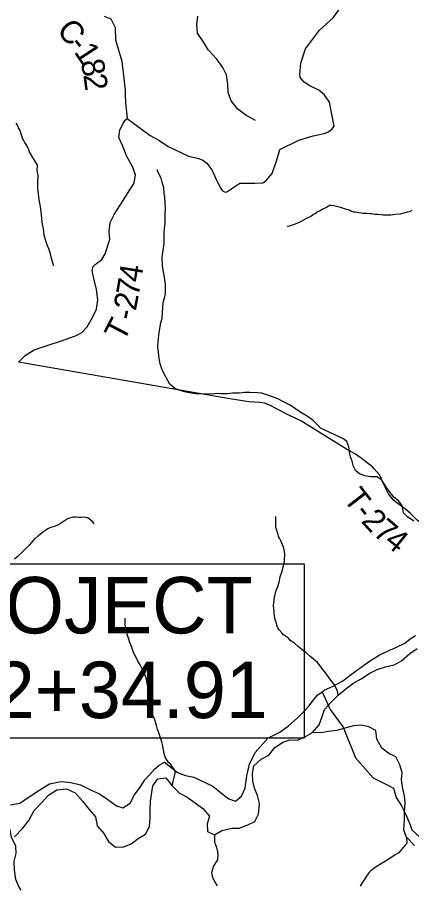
# Model space of a CAD drawing. Extents: x 0 to 34, y 0 to 22.
# Drawn here: x 6.694 to 7.671, y 15.248 to 17.398 of the extents above; entities that cross this region are included whole.
import ezdxf

# ---------------------------------------------------------------- set-up
doc = ezdxf.new("R2010")
doc.units = 0
for name, color, linetype in [('GM_X_County_Road', 7, 'Continuous'), ('GM_X_County_Road_Text', 7, 'Continuous'), ('GM_X_Major_River', 7, 'Continuous'), ('GM_X_Minor_River', 7, 'Continuous'), ('GM_X_Township_Road', 7, 'Continuous'), ('GM_X_Township_Road_Text', 7, 'Continuous'), ('SH_Masking', 7, 'Continuous'), ('SH_Text', 7, 'Continuous')]:
    doc.layers.add(name, color=color, linetype=linetype)

msp = doc.modelspace()

# ---------------------------------------------------------------- linework, layer by layer
at = {"layer": 'GM_X_County_Road'}
for points in [[(6.9615, 17.2059), (6.9619, 17.1873), (6.9657, 17.148), (7.0231, 17.1057), (7.0448, 17.0937), (7.0678, 17.078), (7.0956, 17.0653), (7.1185, 17.0545), (7.144, 17.0486), (7.1534, 17.0446), (7.1635, 17.0366), (7.1762, 17.0208), (7.1901, 16.9901), (7.1979, 16.9738), (7.2028, 16.9683), (7.209, 16.9652), (7.2135, 16.9656), (7.2453, 16.9872), (7.2829, 16.9875), (7.3023, 16.9884), (7.3096, 16.993), (7.3209, 17.0055), (7.3253, 17.0115), (7.3375, 17.0454), (7.3449, 17.0709), (7.3918, 17.0941), (7.4274, 17.1047), (7.4548, 17.1103), (7.4653, 17.1149), (7.4746, 17.1224), (7.4789, 17.1284), (7.4678, 17.1883), (7.4546, 17.2069), (7.4413, 17.2181), (7.4188, 17.229), (7.4046, 17.2376), (7.3953, 17.2494), (7.3942, 17.2565), (7.3966, 17.285), (7.4081, 17.3201), (7.443, 17.3664), (7.477, 17.3975), (7.4972, 17.4258)], [(6.909, 17.4016), (6.9255, 17.3945), (6.9367, 17.3737), (6.937, 17.3429), (6.9527, 17.2902), (6.9613, 17.2177), (6.9615, 17.2059)], [(6.6999, 15.4504), (6.7429, 15.4793), (6.7737, 15.4979), (6.8022, 15.5039), (6.8261, 15.502), (6.8504, 15.4955), (6.8754, 15.4834), (6.8975, 15.4731), (6.9183, 15.4598), (6.94, 15.4435), (6.9552, 15.4385), (6.9738, 15.4507), (6.9844, 15.4712), (6.9981, 15.4898), (7.0095, 15.508), (7.0225, 15.5217), (7.035, 15.5353), (7.0456, 15.5448), (7.0582, 15.5524), (7.0745, 15.5395), (7.0912, 15.5262), (7.1106, 15.5186), (7.1311, 15.5148), (7.1785, 15.4924), (7.2009, 15.4745), (7.2184, 15.4608), (7.2347, 15.4555), (7.2495, 15.4677), (7.2583, 15.4878), (7.2625, 15.5181), (7.269, 15.547), (7.2834, 15.5759), (7.315, 15.6112), (7.3442, 15.6267), (7.3659, 15.6423), (7.3876, 15.6613), (7.4058, 15.6791), (7.4172, 15.6916), (7.4256, 15.703), (7.4389, 15.7186), (7.4491, 15.7265), (7.4545, 15.7307), (7.4788, 15.741), (7.5008, 15.7539), (7.5221, 15.7702), (7.5666, 15.8028), (7.5905, 15.8172), (7.6099, 15.8267), (7.6338, 15.8374), (7.6547, 15.8472), (7.668, 15.8575), (7.6806, 15.8662)], [(6.6768, 15.4459), (6.6999, 15.4504)]]:
    msp.add_lwpolyline(points, dxfattribs=at)
at = {"layer": 'GM_X_Major_River'}
for points in [[(7.0234, 15.4144), (7.0227, 15.4349), (7.0235, 15.4546), (7.0266, 15.472), (7.0297, 15.4932), (7.0419, 15.5106), (7.0623, 15.5128), (7.0774, 15.4931), (7.0955, 15.4748), (7.1144, 15.4649), (7.1348, 15.4512), (7.1537, 15.4375), (7.1703, 15.4185), (7.1642, 15.3988), (7.1649, 15.3798), (7.1822, 15.3722), (7.2004, 15.3828), (7.2262, 15.3888), (7.2436, 15.3887), (7.2648, 15.397), (7.2823, 15.4053), (7.2914, 15.4227), (7.2938, 15.4492), (7.2893, 15.4697), (7.2818, 15.4872), (7.2773, 15.5046), (7.2766, 15.5236), (7.2797, 15.5426), (7.2986, 15.5592), (7.3176, 15.5697), (7.3313, 15.5879), (7.3518, 15.6015), (7.3692, 15.6075), (7.3881, 15.6067), (7.4078, 15.6157), (7.4253, 15.6256), (7.442, 15.6445), (7.4496, 15.6649), (7.455, 15.6823), (7.4709, 15.6997), (7.4891, 15.7179), (7.5081, 15.7338), (7.5256, 15.7474), (7.546, 15.7587), (7.5673, 15.7723), (7.5855, 15.7821), (7.6067, 15.7881), (7.6279, 15.7933), (7.6461, 15.8031), (7.6666, 15.8213), (7.6848, 15.8341)], [(6.6864, 15.3668), (6.7062, 15.3873), (6.7221, 15.4077), (6.7358, 15.4319), (6.754, 15.4508), (6.7708, 15.4705), (6.792, 15.4833), (6.8155, 15.4863), (6.8374, 15.4763), (6.8562, 15.4543), (6.8721, 15.4345), (6.8872, 15.4163), (6.8916, 15.3943), (6.9082, 15.3753), (6.9195, 15.3555), (6.9369, 15.3411), (6.9581, 15.3425), (6.9763, 15.3493), (6.9937, 15.3629), (7.0112, 15.3735), (7.0211, 15.3924), (7.0234, 15.4144)]]:
    msp.add_lwpolyline(points, dxfattribs=at)
at = {"layer": 'GM_X_Minor_River'}
for points in [[(7.2846, 17.1431), (7.2605, 17.1561), (7.2408, 17.1706), (7.2235, 17.1919), (7.2167, 17.2124), (7.216, 17.2329), (7.2123, 17.2557), (7.2033, 17.2739), (7.1882, 17.2944), (7.1671, 17.318), (7.1558, 17.3363), (7.1407, 17.3591), (7.1385, 17.3804), (7.1409, 17.4016)], [(6.6899, 17.1364), (6.694, 17.1306), (6.6969, 17.123), (6.6998, 17.1184), (6.7023, 17.11), (6.7063, 17.0974), (6.7092, 17.0931), (6.7118, 17.0882), (6.7151, 17.0832), (6.7188, 17.0766), (6.7214, 17.0705), (6.7239, 17.0636)], [(6.7239, 17.0636), (6.7429, 17.0316), (6.7425, 17.0187), (6.7444, 17.0066), (6.744, 16.9888), (6.7436, 16.9744), (6.7452, 16.9607), (6.7474, 16.946), (6.7493, 16.9335), (6.7512, 16.9232), (6.7527, 16.9107), (6.7538, 16.8978), (6.7554, 16.8861), (6.7576, 16.8739), (6.7595, 16.8595), (6.7629, 16.8474), (6.7667, 16.8357), (6.7709, 16.8258), (6.7746, 16.8152), (6.7765, 16.805), (6.7799, 16.7928), (6.7837, 16.7834), (6.7837, 16.7837)], [(7.6771, 16.1491), (7.6608, 16.1604), (7.6514, 16.1699), (7.6495, 16.1797), (7.6468, 16.1892), (7.6385, 16.1998), (7.6268, 16.2089), (7.6188, 16.2195), (7.6105, 16.2301), (7.5977, 16.251), (7.5848, 16.2593), (7.5693, 16.2597), (7.5556, 16.262), (7.5424, 16.2665), (7.5322, 16.2748), (7.5269, 16.2851), (7.5235, 16.2983), (7.5193, 16.3112), (7.5171, 16.3218), (7.5155, 16.334), (7.5103, 16.3468), (7.5004, 16.3548), (7.4838, 16.362), (7.4671, 16.3699), (7.4561, 16.3753), (7.4455, 16.3798), (7.4372, 16.3893), (7.4262, 16.3995), (7.4119, 16.4097), (7.3967, 16.4188), (7.3831, 16.4279), (7.3699, 16.437), (7.3555, 16.4442), (7.3392, 16.4525), (7.3195, 16.4605), (7.3097, 16.4635), (7.2995, 16.4666), (7.2889, 16.4677), (7.2703, 16.4685), (7.2575, 16.4681), (7.2435, 16.4669), (7.2276, 16.4666), (7.2136, 16.4654), (7.1988, 16.4651), (7.1886, 16.4658), (7.1746, 16.4647), (7.1572, 16.4651), (7.1401, 16.4647), (7.1258, 16.4666), (7.1121, 16.4696), (7.0974, 16.473), (7.0841, 16.4787), (7.0716, 16.4893), (7.0584, 16.5128), (7.0516, 16.5272), (7.0478, 16.5393), (7.0455, 16.5533), (7.0437, 16.5674), (7.0422, 16.5825), (7.0437, 16.6034), (7.0456, 16.6162), (7.0467, 16.6272), (7.0497, 16.6413), (7.0528, 16.653), (7.0535, 16.667), (7.0543, 16.6788), (7.055, 16.6917), (7.0588, 16.7023), (7.0607, 16.714), (7.0615, 16.7239), (7.0615, 16.7368), (7.0596, 16.7474), (7.0581, 16.7591), (7.0551, 16.7716), (7.0539, 16.7834), (7.0532, 16.8046), (7.0551, 16.8205), (7.0577, 16.8376), (7.0581, 16.8504), (7.0577, 16.8645), (7.0589, 16.8758), (7.06, 16.8876), (7.0604, 16.8978), (7.0604, 16.9103), (7.0612, 16.9247), (7.0604, 16.938), (7.0593, 16.952), (7.0581, 16.963), (7.057, 16.9755), (7.0532, 16.9896), (7.0502, 16.9994), (7.0449, 17.0108), (7.0408, 17.0203), (7.0404, 17.0191)], [(7.6717, 16.9196), (7.6659, 16.9163), (7.6599, 16.9152), (7.6522, 16.9127), (7.6431, 16.9109), (7.6306, 16.9093), (7.6253, 16.9086), (7.6196, 16.9083), (7.6094, 16.9081), (7.5999, 16.9083), (7.595, 16.9087), (7.5878, 16.9096), (7.5802, 16.9101), (7.5723, 16.9114), (7.5674, 16.9115), (7.5591, 16.9124), (7.5515, 16.9125), (7.547, 16.9129), (7.5402, 16.9142), (7.5322, 16.9151), (7.5281, 16.9159), (7.5224, 16.9175), (7.5183, 16.9195), (7.5107, 16.9219), (7.5051, 16.9235), (7.4979, 16.9259), (7.4919, 16.9276), (7.4855, 16.9299), (7.4787, 16.9316), (7.4719, 16.9321), (7.4677, 16.9318), (7.4624, 16.9284), (7.4582, 16.9262), (7.4509, 16.9233), (7.4429, 16.9177), (7.4375, 16.9155), (7.4322, 16.9115), (7.428, 16.9096), (7.4211, 16.9044), (7.4138, 16.9011), (7.4073, 16.8978), (7.4012, 16.8945), (7.3954, 16.8912), (7.3882, 16.8879), (7.3825, 16.8857), (7.3779, 16.8843), (7.3726, 16.8821), (7.368, 16.881), (7.363, 16.8799)], [(6.6865, 16.0564), (6.6957, 16.0639), (6.7038, 16.0713), (6.7088, 16.0758), (6.7165, 16.0836), (6.7238, 16.09), (6.7296, 16.0967), (6.7342, 16.1016), (6.7381, 16.1061), (6.7454, 16.1135), (6.7523, 16.1187), (6.7593, 16.1243), (6.7666, 16.1299), (6.7708, 16.1317), (6.7803, 16.1354), (6.7868, 16.1368), (6.7955, 16.1416), (6.8005, 16.1449), (6.8055, 16.1478), (6.8097, 16.1504), (6.8174, 16.1556), (6.8239, 16.1578), (6.8326, 16.1599), (6.8398, 16.1602), (6.8455, 16.1597), (6.8527, 16.1596), (6.8569, 16.1603), (6.8629, 16.1594), (6.8674, 16.1582), (6.8719, 16.1558), (6.8786, 16.15), (6.8838, 16.1431)], [(7.4891, 15.7179), (7.4875, 15.7288), (7.4846, 15.7349), (7.4813, 15.7429), (7.4735, 15.7522), (7.4668, 15.761), (7.4617, 15.7676), (7.4561, 15.776), (7.4506, 15.7826), (7.4446, 15.7906), (7.4376, 15.7991), (7.4279, 15.8076), (7.4193, 15.815), (7.41, 15.8228), (7.3999, 15.8309), (7.3898, 15.839), (7.3809, 15.8472), (7.37, 15.8538), (7.3659, 15.8592), (7.3539, 15.8674), (7.3495, 15.8728), (7.3428, 15.8801), (7.3388, 15.887), (7.337, 15.892), (7.3359, 15.8969), (7.333, 15.9057), (7.3317, 15.9145), (7.3306, 15.9202), (7.3303, 15.9244), (7.3293, 15.9327), (7.3291, 15.9403), (7.3296, 15.9472), (7.3305, 15.9544), (7.3317, 15.9616), (7.333, 15.9672), (7.3342, 15.9725), (7.3366, 15.9793), (7.3394, 15.9876), (7.3426, 15.9986), (7.3455, 16.0115), (7.3503, 16.0251), (7.3528, 16.0364), (7.3552, 16.0455), (7.356, 16.0508), (7.3565, 16.0569), (7.357, 16.0629), (7.3571, 16.069), (7.3554, 16.0785), (7.354, 16.0846), (7.3514, 16.0911), (7.3478, 16.0992), (7.3434, 16.1076), (7.3416, 16.1118), (7.3401, 16.116), (7.3387, 16.1217), (7.3362, 16.1294), (7.3348, 16.1339), (7.3349, 16.1613)], [(7.0774, 15.4931), (7.0851, 15.5248), (7.0847, 15.529), (7.0826, 15.5347), (7.0781, 15.5398), (7.0741, 15.5459), (7.0688, 15.5509), (7.0663, 15.5551), (7.0615, 15.5628), (7.0593, 15.5674), (7.0579, 15.5739), (7.0565, 15.5823), (7.0548, 15.5907), (7.0534, 15.596), (7.0516, 15.6025), (7.0498, 15.6097), (7.0469, 15.6174), (7.0455, 15.6223), (7.044, 15.6269), (7.0415, 15.6334), (7.0387, 15.6433), (7.0369, 15.6491), (7.0343, 15.6567), (7.0314, 15.664), (7.0289, 15.6708), (7.0268, 15.6781), (7.025, 15.6846), (7.0241, 15.6964), (7.023, 15.7017), (7.0217, 15.712), (7.02, 15.7219), (7.019, 15.731), (7.0173, 15.7405), (7.0159, 15.7474), (7.0148, 15.7524), (7.0138, 15.7577), (7.0113, 15.7653), (7.008, 15.7734), (7.0036, 15.7833), (6.9981, 15.7933), (6.9922, 15.8025), (6.9864, 15.8144), (6.982, 15.8236), (6.9784, 15.8335), (6.9755, 15.843), (6.9722, 15.8503), (6.9705, 15.8579), (6.9668, 15.866), (6.9651, 15.874), (6.9629, 15.882), (6.9623, 15.8862), (6.9613, 15.8938), (6.9611, 15.9094)], [(7.6787, 15.3457), (7.6583, 15.3663), (7.6523, 15.3837), (7.6532, 15.4088), (7.654, 15.43), (7.6556, 15.4512), (7.6534, 15.4687), (7.6496, 15.4861), (7.6459, 15.5081), (7.6475, 15.5263), (7.6423, 15.5453), (7.6325, 15.565), (7.6151, 15.5734), (7.597, 15.5871), (7.5849, 15.6092), (7.5827, 15.6304), (7.5653, 15.6396), (7.5472, 15.6434), (7.5275, 15.6419), (7.5055, 15.6367), (7.4858, 15.6307), (7.4654, 15.6277), (7.4465, 15.6247), (7.4253, 15.6256)], [(7.1822, 15.3722), (7.1828, 15.3527), (7.1853, 15.3481), (7.1875, 15.3404), (7.1903, 15.3294), (7.1909, 15.321), (7.1904, 15.3149), (7.1896, 15.3096), (7.1869, 15.3051), (7.1826, 15.2987), (7.1794, 15.2931), (7.1778, 15.2863), (7.1754, 15.2787), (7.1771, 15.2692), (7.1807, 15.2593), (7.1852, 15.252), (7.1888, 15.2455)], [(7.6583, 15.3663), (7.6592, 15.3503), (7.6546, 15.3454), (7.6507, 15.3406), (7.6465, 15.3357), (7.6395, 15.3274), (7.6307, 15.3219), (7.6223, 15.3167), (7.6127, 15.3108), (7.602, 15.3038), (7.5943, 15.2994), (7.5836, 15.2927), (7.5771, 15.2879), (7.5705, 15.2823), (7.5651, 15.2774), (7.5613, 15.2722), (7.555, 15.2628), (7.5492, 15.2542), (7.5441, 15.2448)]]:
    msp.add_lwpolyline(points, dxfattribs=at)
at = {"layer": 'GM_X_Township_Road'}
msp.add_line((7.2207, 16.4531), (6.7536, 16.5335), dxfattribs=at)
for points in [[(6.881, 16.7625), (6.8792, 16.7708), (6.8815, 16.781), (6.8898, 16.7886), (6.9032, 16.7981), (6.9119, 16.8125), (6.9229, 16.8475), (6.9218, 16.8676), (6.9241, 16.89), (6.934, 16.9098), (6.9564, 16.9447), (6.9709, 16.9687), (6.9834, 16.9877), (6.9865, 17.0078), (6.9793, 17.0291), (6.9649, 17.0534), (6.9543, 17.0804), (6.9452, 17.1005), (6.9479, 17.1188), (6.9551, 17.1347), (6.9612, 17.1435), (6.9657, 17.148)], [(6.7536, 16.5335), (6.6967, 16.5433), (6.7134, 16.5604), (6.7358, 16.5741), (6.7723, 16.587), (6.8008, 16.5961), (6.8213, 16.6029), (6.838, 16.609), (6.8525, 16.6162), (6.8666, 16.6314), (6.8799, 16.6542), (6.8898, 16.6754), (6.8936, 16.6978), (6.8902, 16.7237), (6.8841, 16.748), (6.881, 16.7625)], [(7.5441, 16.3069), (7.5321, 16.3159), (7.5097, 16.3277), (7.4448, 16.3683), (7.3966, 16.3984), (7.3654, 16.4132), (7.3377, 16.4272), (7.321, 16.436), (7.3062, 16.4417), (7.2959, 16.444), (7.2675, 16.4451), (7.2207, 16.4531)], [(7.7559, 16.1046), (7.7328, 16.1199), (7.7028, 16.1385), (7.6858, 16.1514), (7.6687, 16.1685), (7.6558, 16.1795), (7.6379, 16.1924), (7.6266, 16.2015), (7.6137, 16.2171), (7.603, 16.2388), (7.5913, 16.2642), (7.5784, 16.2795), (7.5746, 16.284), (7.5611, 16.2941), (7.5484, 16.3037), (7.5441, 16.3069)], [(7.4491, 15.7265), (7.4691, 15.6826), (7.5015, 15.6388), (7.532, 15.5626), (7.5758, 15.5131), (7.612, 15.4947)], [(7.612, 15.4947), (7.6267, 15.4872), (7.6328, 15.4648), (7.646, 15.444), (7.6559, 15.4242), (7.6676, 15.3965), (7.6718, 15.3843), (7.6915, 15.3661), (7.7405, 15.3239), (7.7614, 15.3095), (7.7826, 15.2996), (7.8024, 15.2882), (7.8157, 15.2758)], [(6.703, 15.2346), (6.6971, 15.2435), (6.6903, 15.2613), (6.6869, 15.2849), (6.6861, 15.3058), (6.6907, 15.3255), (6.69, 15.3441), (6.6797, 15.3658), (6.6718, 15.4022), (6.6604, 15.447)]]:
    msp.add_lwpolyline(points, dxfattribs=at)
at = {"layer": 'SH_Masking'}
msp.add_lwpolyline([(5.9375, 16.0436), (7.4049, 16.0436), (7.4049, 15.6115), (5.9375, 15.6115)], close=True, dxfattribs=at)
at = {"layer": 'SH_Text'}
msp.add_lwpolyline([(5.9375, 16.0436), (7.4049, 16.0436), (7.4049, 15.6115), (5.9375, 15.6115)], close=True, dxfattribs=at)

# ---------------------------------------------------------------- texts
at = {"layer": 'GM_X_County_Road_Text'}
for s, rotation, p in [('C', 310.096, (6.7892, 17.3653)), ('-', 309.2096, (6.8191, 17.3298)), ('1', 303.5999, (6.833, 17.3129)), ('8', 282.191, (6.8502, 17.2889)), ('2', 277.1533, (6.8574, 17.256))]:
    msp.add_text(s, height=0.0568, rotation=rotation, dxfattribs=at).set_placement(p)
at = {"layer": 'GM_X_Township_Road_Text'}
for s, rotation, p in [('4', 80.5428, (7, 16.7394)), ('7', 80.3334, (6.9941, 16.7047)), ('2', 79.4819, (6.9875, 16.6693)), ('-', 78.0268, (6.9824, 16.645)), ('T', 62.5643, (6.9572, 16.5916)), ('T', 307.4751, (7.5, 16.2047)), ('-', 308.7263, (7.5267, 16.1699)), ('2', 312.5788, (7.544, 16.1485)), ('7', 319.5388, (7.5731, 16.1175)), ('4', 320.7602, (7.6008, 16.094))]:
    msp.add_text(s, height=0.0568, rotation=rotation, dxfattribs=at).set_placement(p)
at = {"layer": 'SH_Text'}
for s, p in [('END PROJECT', (5.9565, 15.8712)), ('STA. 102+34.91', (5.9565, 15.6612))]:
    msp.add_text(s, height=0.14, dxfattribs=at).set_placement(p)

doc.saveas('drawing.dxf')
